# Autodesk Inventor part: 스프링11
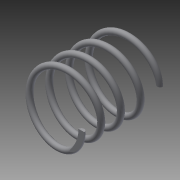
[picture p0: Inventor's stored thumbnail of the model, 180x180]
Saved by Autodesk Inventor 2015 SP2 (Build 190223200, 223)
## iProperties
Created: 2015-06
Part Number: 스프링11
Material: 일반
Document SubType Name: Modeling
Designer: AMC
Density: 1 g/cm^3
Appearance: 기본값
Author: AMC
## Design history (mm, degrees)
sketch "스케치1"
  geometry: L1 (0, 0)-(8, 0); L2 (0, 0)-(0, 14.102); C1 r 0.75 at (8, 0)
  constraints: 4 end point, 1 centre point, 1 coincident, 1 horizontal, 1 vertical
  dimensions: "d0" = 8 distance of L1.start L1.end; "d1" = 1.5 diameter of C1
feature "코일1" sketch "스케치1" pitch "d2" = 10; turns "d4" = 4; dims "d3" = 20.5 (= aa), "d5" = 0, angle "d6" = 90 deg, angle "d7" = 90 deg, "d8" = 0, "d9" = 0
sketch "스케치2"
  geometry: L1 (2.181, 0)-(-17.271, 0); L2 (-17.271, 0)-(-17.271, -4.707); L3 (-17.271, -4.707)-(2.181, -4.707); L4 (2.181, -4.707)-(2.181, 0); L5 (3.025, 20.5)-(-21.212, 20.5); L6 (-21.212, 20.5)-(-21.212, 25.441); L7 (-21.212, 25.441)-(3.025, 25.441); L8 (3.025, 25.441)-(3.025, 20.5); C1 r 0.75 at (0, 0) reference; C2 r 0.75 at (0, 20.5) reference; 8 further points
  constraints: 16 end point, 4 parallel, 2 horizontal, 2 perpendicular, 1 point on line, 7 other
  dimensions: "d10" = 20.5 distance between parallel lines of L1 L5 (= aa)
extrude "돌출1" cut sketch "스케치2" stored distance "d11" = 50; taper "d12" = 0 deg
node "솔리드1"
node "절단 모서리 투영1"
other parameters: "aa" = 20.5 [user parameter; used in 2 equation terms]
